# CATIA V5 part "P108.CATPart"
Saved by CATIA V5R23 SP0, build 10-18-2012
Part number: P108
Definition: Goupille mécanindus D5
Description: Goupille mécanindus D5
Bounding box of the stored display mesh (mm): x -3 to 3, y -2.954 to 2.954, z -16 to 16
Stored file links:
  C:\wamp\www\COURS\CONCEPTION GMP1\TITRE 02-SEMESTRE 2\03-TP7-PRESSE MECANIQUE\eleve\P108.CATPart
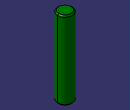
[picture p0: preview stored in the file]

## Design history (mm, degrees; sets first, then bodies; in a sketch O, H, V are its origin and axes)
Body1 (main body)
  Sketch1 on xy-plane, origin (0, 0, 0), H (1, 0, 0), V (0, 1, 0)
    circle A1 centre (0, 0) radius 3
    radius A1 = 3
  Pad1: profile Sketch1, direction (0, 0, 1), length 16, mirrored extent
  Chamfer1: length 0.5, angle 45, on edge [face of Pad1 | face of Pad1] (x2)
